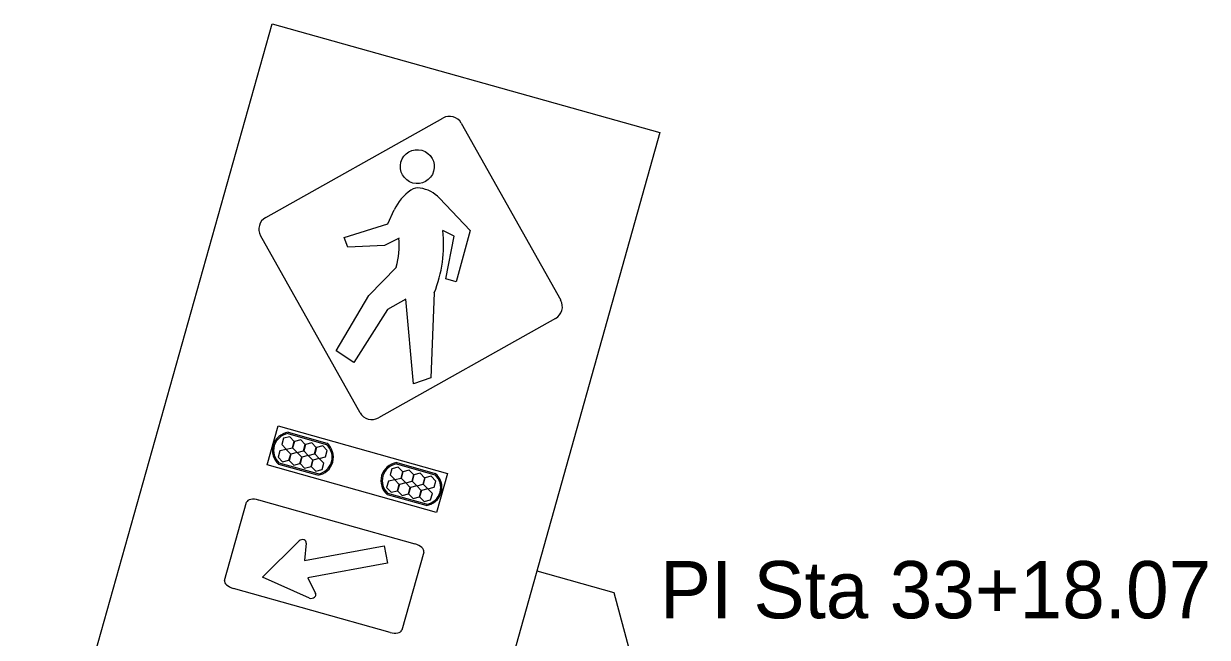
# Model space of a CAD drawing. Extents: x 902965 to 1126554, y 597041 to 686906.
# Drawn here: x 930066.2 to 930210.9, y 685815.7 to 685890.7 of the extents above; entities that cross this region are included whole.
import ezdxf

# ---------------------------------------------------------------- set-up
doc = ezdxf.new("R2010")
doc.units = 0
for name, color, linetype in [('CTL North Arrow CELL', 7, 'Continuous'), ('Default', 7, 'Continuous'), ('Exist Horizontal Alignment Curve and Spiral Data', 7, 'Continuous'), ('Exist Utilities Water Meter CELL', 7, 'Continuous'), ('Prop DSN Text', 7, 'Continuous'), ('WS W11-2 CELL', 7, 'Continuous'), ('WS W16-7p CELL', 7, 'Continuous')]:
    doc.layers.add(name, color=color, linetype=linetype)

msp = doc.modelspace()

# ---------------------------------------------------------------- linework, layer by layer
at = {"layer": 'CTL North Arrow CELL'}
for p, q in [((930066.22, 685782.66), (930096.58, 685890.74)), ((930096.58, 685890.74), (930144.01, 685877.42)), ((930144.01, 685877.42), (930113.65, 685769.34))]:
    msp.add_line(p, q, dxfattribs=at)
at = {"layer": 'Default'}
for points in [[(930116.7, 685830.95), (930095.99, 685836.77), (930097.33, 685841.54), (930118.04, 685835.73)], [(930099.3, 685839.64), (930098.75, 685840.21), (930097.98, 685840.02), (930097.76, 685839.25), (930098.31, 685838.68), (930099.09, 685838.87)], [(930100.65, 685839.25), (930100.09, 685839.83), (930099.32, 685839.63), (930099.1, 685838.86), (930099.66, 685838.29), (930100.43, 685838.49)], [(930101.99, 685838.88), (930101.44, 685839.45), (930100.67, 685839.25), (930100.45, 685838.49), (930101, 685837.91), (930101.78, 685838.11)], [(930098.87, 685838.09), (930098.32, 685838.66), (930097.54, 685838.47), (930097.33, 685837.7), (930097.88, 685837.13), (930098.65, 685837.33)], [(930100.22, 685837.71), (930099.66, 685838.28), (930098.89, 685838.09), (930098.67, 685837.32), (930099.23, 685836.75), (930100, 685836.95)], [(930103.34, 685838.51), (930102.79, 685839.08), (930102.01, 685838.88), (930101.8, 685838.11), (930102.35, 685837.54), (930103.13, 685837.74)], [(930101.56, 685837.34), (930101.01, 685837.91), (930100.23, 685837.72), (930100.02, 685836.95), (930100.57, 685836.38), (930101.35, 685836.57)], [(930102.91, 685836.96), (930102.36, 685837.53), (930101.59, 685837.34), (930101.37, 685836.57), (930101.93, 685836), (930102.7, 685836.2)], [(930112.57, 685835.93), (930112.01, 685836.5), (930111.24, 685836.3), (930111.02, 685835.54), (930111.58, 685834.97), (930112.35, 685835.16)], [(930113.91, 685835.54), (930113.36, 685836.11), (930112.59, 685835.92), (930112.37, 685835.15), (930112.92, 685834.58), (930113.7, 685834.78)], [(930115.26, 685835.16), (930114.7, 685835.74), (930113.93, 685835.54), (930113.71, 685834.77), (930114.27, 685834.2), (930115.04, 685834.4)], [(930116.61, 685834.79), (930116.05, 685835.37), (930115.28, 685835.17), (930115.06, 685834.4), (930115.62, 685833.83), (930116.39, 685834.03)], [(930112.14, 685834.38), (930111.58, 685834.95), (930110.81, 685834.76), (930110.59, 685833.99), (930111.15, 685833.42), (930111.92, 685833.61)], [(930113.48, 685834), (930112.93, 685834.57), (930112.15, 685834.38), (930111.94, 685833.61), (930112.49, 685833.04), (930113.26, 685833.23)], [(930114.83, 685833.63), (930114.27, 685834.2), (930113.5, 685834), (930113.28, 685833.24), (930113.84, 685832.67), (930114.61, 685832.86)], [(930116.18, 685833.25), (930115.62, 685833.82), (930114.85, 685833.63), (930114.63, 685832.86), (930115.19, 685832.29), (930115.96, 685832.48)]]:
    msp.add_lwpolyline(points, close=True, dxfattribs=at)
at = {"layer": 'Exist Utilities Water Meter CELL'}
for p, q in [((930100.36, 685838.13), (930100.36, 685838.13)), ((930113.63, 685834.42), (930113.63, 685834.42))]:
    msp.add_line(p, q, dxfattribs=at)
for points in [[(930098.52, 685840.59), (930103.22, 685839.27)], [(930098.56, 685840.75), (930103.27, 685839.43)], [(930102.16, 685835.5), (930097.43, 685836.83)], [(930102.21, 685835.66), (930097.47, 685836.99)], [(930111.78, 685836.88), (930116.49, 685835.56)], [(930111.83, 685837.04), (930116.53, 685835.72)], [(930115.43, 685831.79), (930110.69, 685833.12)], [(930115.47, 685831.95), (930110.74, 685833.28)]]:
    msp.add_lwpolyline(points, dxfattribs=at)
for centre, radius, start, end in [((930098.85, 685838.54), 2.23, 97.4886, 230.29), ((930098.86, 685838.54), 2.08, 99.6115, 228.093), ((930101.86, 685837.71), 2.23, 277.9589, 50.619), ((930101.87, 685837.7), 2.07, 279.4378, 49.1834), ((930112.12, 685834.83), 2.23, 97.4886, 230.29), ((930112.13, 685834.83), 2.08, 99.6115, 228.093), ((930115.12, 685834), 2.23, 277.9589, 50.619), ((930115.14, 685833.99), 2.07, 279.4378, 49.1834)]:
    msp.add_arc(centre, radius, start, end, dxfattribs=at)
at = {"layer": 'Prop DSN Text'}
msp.add_line((930128.95, 685823.8), (930138.36, 685821.16), dxfattribs=at)
msp.add_lwpolyline([(930138.36, 685821.16), (930164.82, 685722.62)], dxfattribs=at)
at = {"layer": 'WS W11-2 CELL'}
for p, q in [((930117.05, 685869.4), (930120.8, 685865.44)), ((930120.8, 685865.44), (930117.05, 685869.4)), ((930117.05, 685869.4), (930120.8, 685865.44)), ((930110.73, 685866.27), (930111.52, 685867.96)), ((930105.41, 685864.59), (930110.73, 685866.27)), ((930118.83, 685864.73), (930117.45, 685865.43)), ((930120.8, 685865.44), (930119.1, 685859.17)), ((930105.83, 685863.4), (930105.41, 685864.59)), ((930112.11, 685864.49), (930110.34, 685863.6)), ((930117.81, 685859.53), (930118.83, 685864.73)), ((930110.34, 685863.6), (930105.83, 685863.4)), ((930108.4, 685857.5), (930111.78, 685860.97)), ((930119.1, 685859.17), (930117.81, 685859.53)), ((930104.42, 685850.73), (930108.4, 685857.5)), ((930112.95, 685857.04), (930110.7, 685855.78)), ((930113.89, 685846.68), (930112.95, 685857.04)), ((930116.41, 685857.82), (930115.99, 685847.42)), ((930110.7, 685855.78), (930106.6, 685849.29)), ((930131.24, 685854.68), (930109.58, 685842.51)), ((930131.24, 685854.68), (930109.58, 685842.51)), ((930106.6, 685849.29), (930104.42, 685850.73)), ((930115.99, 685847.42), (930113.89, 685846.68))]:
    msp.add_line(p, q, dxfattribs=at)
for points in [[(930095.81, 685867.04), (930117.47, 685879.2)], [(930119.71, 685878.57), (930131.87, 685856.91)], [(930107.34, 685843.14), (930095.18, 685864.81)]]:
    msp.add_lwpolyline(points, dxfattribs=at)
for centre, major_axis, start_param, end_param in [((930118.28, 685877.77), (0.44, 1.58), 6.283072, 7.068583), ((930118.28, 685877.77), (0.44, 1.58), 5.49756, 6.283072), ((930116.98, 685865.4), (-1.63, -5.81), 4.017186, 4.547553), ((930114.46, 685869.07), (-0.43, -1.52), 3.261682, 4.017186), ((930114.07, 685866.58), (1.11, 3.95), 5.744678, 6.403274), ((930096.61, 685865.61), (0.44, 1.58), 0.785398, 2.356194), ((930102, 685863.66), (4.21, 14.97), 4.60131, 5.100443), ((930102, 685863.66), (2.74, 9.76), 4.717416, 5.067864), ((930130.44, 685856.11), (0.44, 1.58), 3.926991, 5.497787), ((930108.78, 685843.95), (-0.44, -1.58), 5.497787, 6.283185), ((930108.78, 685843.95), (-0.44, -1.58), 6.283185, 7.068583)]:
    msp.add_ellipse(centre, major_axis=major_axis, ratio=0.999996, start_param=start_param, end_param=end_param, dxfattribs=at)
msp.add_ellipse((930114.34, 685873.25), major_axis=(0.56, 2), ratio=0.999996, dxfattribs=at)
at = {"layer": 'WS W16-7p CELL'}
for p, q in [((930095.43, 685823.03), (930099.88, 685827.49)), ((930100.76, 685827.21), (930100.56, 685825.06)), ((930100.56, 685825.06), (930110.3, 685826.86)), ((930110.3, 685826.86), (930110.69, 685824.73)), ((930110.69, 685824.73), (930100.95, 685822.93)), ((930101.18, 685820.46), (930095.43, 685823.03)), ((930100.95, 685822.93), (930101.9, 685821.03)), ((930101.44, 685818.96), (930091.87, 685821.64)), ((930111.01, 685816.27), (930101.44, 685818.96))]:
    msp.add_line(p, q, dxfattribs=at)
for points in [[(930090.79, 685822.63), (930093.47, 685832.2)], [(930094.91, 685832.48), (930104.48, 685829.79)], [(930104.48, 685829.79), (930114.05, 685827.1)], [(930115.13, 685826.11), (930112.45, 685816.55)]]:
    msp.add_lwpolyline(points, dxfattribs=at)
for centre, major_axis, ratio, start_param, end_param in [((930094.74, 685831.84), (-1.26, 0.35), 0.5, 4.712162, 6.283185), ((930100.24, 685827.23), (-0.525, -0.097), 0.720018, 2.830617, 5.313577), ((930113.87, 685826.47), (1.26, -0.35), 0.5, 0, 1.570796), ((930092.05, 685822.28), (-1.26, 0.35), 0.5, 0, 1.570796), ((930101.42, 685820.83), (-0.525, -0.097), 0.720018, 0.96961, 3.452569), ((930111.18, 685816.9), (-1.26, 0.35), 0.5, 1.570796, 3.141593)]:
    msp.add_ellipse(centre, major_axis=major_axis, ratio=ratio, start_param=start_param, end_param=end_param, dxfattribs=at)

# ---------------------------------------------------------------- texts
at = {"layer": 'Exist Horizontal Alignment Curve and Spiral Data'}
msp.add_text('PI Sta 33+18.07', height=7, dxfattribs=at).set_placement((930144, 685818))

doc.saveas('drawing.dxf')
